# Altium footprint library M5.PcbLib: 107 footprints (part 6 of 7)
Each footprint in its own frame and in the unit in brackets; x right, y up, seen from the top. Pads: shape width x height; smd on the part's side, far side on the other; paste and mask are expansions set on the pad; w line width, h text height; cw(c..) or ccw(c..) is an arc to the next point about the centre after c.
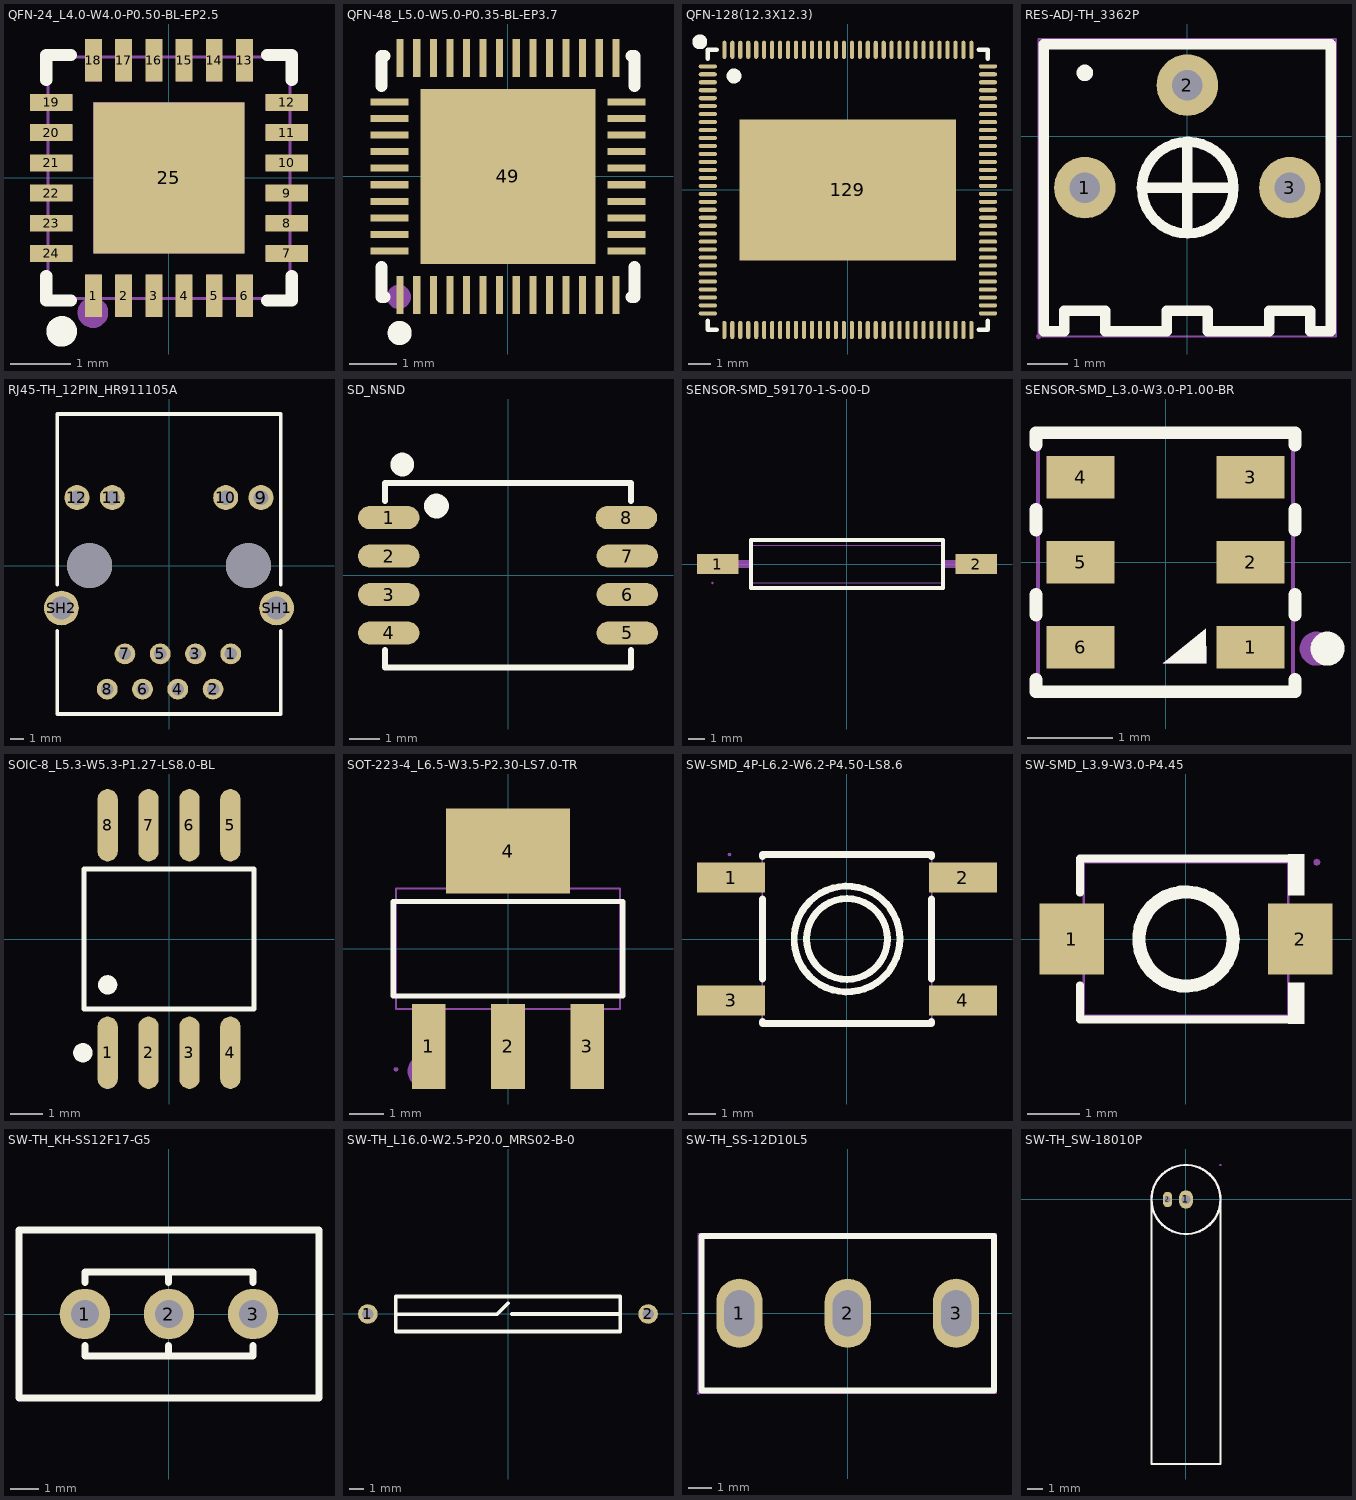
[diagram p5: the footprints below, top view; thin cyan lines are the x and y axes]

## QFN-24_L4.0-W4.0-P0.50-BL-EP2.5 [mm]
pads (25):
  rect 0.28x0.7 smd paste-100 mask+0.05: 1(-1.25,-1.95) 2(-0.75,-1.95) 3(-0.25,-1.95) 4(0.25,-1.95) 5(0.75,-1.95) 6(1.25,-1.95) 13(1.25,1.95) 14(0.75,1.95) 15(0.25,1.95) 16(-0.25,1.95) 17(-0.75,1.95) 18(-1.25,1.95)
  rect 0.7x0.28 smd paste-100 mask+0.05: 7(1.95,-1.25) 8(1.95,-0.75) 9(1.95,-0.25) 10(1.95,0.25) 11(1.95,0.75) 12(1.95,1.25) 19(-1.95,1.25) 20(-1.95,0.75) 21(-1.95,0.25) 22(-1.95,-0.25) 23(-1.95,-0.75) 24(-1.95,-1.25)
  rect 2.5x2.5 smd paste-100 mask+0.05: 25(0,0)
Top Overlay:
  circle w0.254: c-1.778,-2.54 r0.127
  lines w0.2: -2.032,-1.621 -2.032,-2.032 -1.621,-2.032 ; -2.032,1.621 -2.032,2.032 -1.621,2.032 ; 1.621,-2.032 2.032,-2.032 2.032,-1.621 ; 1.621,2.032 2.032,2.032 2.032,1.621
Top Paste:
  region: -1.39,1.6 -1.11,1.6 -1.11,2.3 -1.39,2.3
  region: -0.89,1.6 -0.61,1.6 -0.61,2.3 -0.89,2.3
  region: -0.39,1.6 -0.11,1.6 -0.11,2.3 -0.39,2.3
  region: 0.11,1.6 0.39,1.6 0.39,2.3 0.11,2.3
  region: 0.61,1.6 0.89,1.6 0.89,2.3 0.61,2.3
  region: 1.11,1.6 1.39,1.6 1.39,2.3 1.11,2.3
  region: -1.39,-2.3 -1.11,-2.3 -1.11,-1.6 -1.39,-1.6
  region: -0.89,-2.3 -0.61,-2.3 -0.61,-1.6 -0.89,-1.6
  region: -0.39,-2.3 -0.11,-2.3 -0.11,-1.6 -0.39,-1.6
  region: 0.11,-2.3 0.39,-2.3 0.39,-1.6 0.11,-1.6
  region: 0.61,-2.3 0.89,-2.3 0.89,-1.6 0.61,-1.6
  region: 1.11,-2.3 1.39,-2.3 1.39,-1.6 1.11,-1.6
  region: 1.6,1.39 1.6,1.11 2.3,1.11 2.3,1.39
  region: 1.6,0.89 1.6,0.61 2.3,0.61 2.3,0.89
  region: 1.6,0.39 1.6,0.11 2.3,0.11 2.3,0.39
  region: 1.6,-0.11 1.6,-0.39 2.3,-0.39 2.3,-0.11
  region: 1.6,-0.61 1.6,-0.89 2.3,-0.89 2.3,-0.61
  region: 1.6,-1.11 1.6,-1.39 2.3,-1.39 2.3,-1.11
  region: -2.3,-1.11 -2.3,-1.39 -1.6,-1.39 -1.6,-1.11
  region: -2.3,-0.61 -2.3,-0.89 -1.6,-0.89 -1.6,-0.61
  region: -2.3,-0.11 -2.3,-0.39 -1.6,-0.39 -1.6,-0.11
  region: -2.3,0.39 -2.3,0.11 -1.6,0.11 -1.6,0.39
  region: -2.3,0.89 -2.3,0.61 -1.6,0.61 -1.6,0.89
  region: -2.3,1.39 -2.3,1.11 -1.6,1.11 -1.6,1.39
  region: -1,-1 -1,1 1,1 1,-1
Mechanical 6:
  circle w0.254: c-1.26,-2.23 r0.127
Mechanical 15:
  region: -1.25,-1.25 -1.25,1.25 1.25,1.25 1.25,-1.25
  region: -1.125,-2 -1.375,-2 -1.375,-1.6 -1.125,-1.6
  region: -0.625,-2 -0.875,-2 -0.875,-1.6 -0.625,-1.6
  region: -0.125,-2 -0.375,-2 -0.375,-1.6 -0.125,-1.6
  region: 0.375,-2 0.125,-2 0.125,-1.6 0.375,-1.6
  region: 0.875,-2 0.625,-2 0.625,-1.6 0.875,-1.6
  region: 1.375,-2 1.125,-2 1.125,-1.6 1.375,-1.6
  region: 1.6,-1.375 1.6,-1.125 2,-1.125 2,-1.375
  region: 1.6,-0.875 1.6,-0.625 2,-0.625 2,-0.875
  region: 1.6,-0.375 1.6,-0.125 2,-0.125 2,-0.375
  region: 1.6,0.125 1.6,0.375 2,0.375 2,0.125
  region: 1.6,0.625 1.6,0.875 2,0.875 2,0.625
  region: 1.6,1.125 1.6,1.375 2,1.375 2,1.125
  region: 1.125,2 1.375,2 1.375,1.6 1.125,1.6
  region: 0.625,2 0.875,2 0.875,1.6 0.625,1.6
  region: 0.125,2 0.375,2 0.375,1.6 0.125,1.6
  region: -0.375,2 -0.125,2 -0.125,1.6 -0.375,1.6
  region: -0.875,2 -0.625,2 -0.625,1.6 -0.875,1.6
  region: -1.375,2 -1.125,2 -1.125,1.6 -1.375,1.6
  region: -1.6,1.375 -1.6,1.125 -2,1.125 -2,1.375
  region: -1.6,0.875 -1.6,0.625 -2,0.625 -2,0.875
  region: -1.6,0.375 -1.6,0.125 -2,0.125 -2,0.375
  region: -1.6,-0.125 -1.6,-0.375 -2,-0.375 -2,-0.125
  region: -1.6,-0.625 -1.6,-0.875 -2,-0.875 -2,-0.625
  region: -1.6,-1.125 -1.6,-1.375 -2,-1.375 -2,-1.125
  region: -1.936,-2 -1.954,-1.956 -2,-1.937 -2.046,-1.956 -2.064,-2 -2.046,-2.045 -2,-2.064 -1.954,-2.045
  lines w0.051: -2,-2 -2,2 2,2 2,-2 -2,-2
3D body: height 0.55, standoff 0, extent -2.01,-2.01 2.01,2.01

## QFN-48_L5.0-W5.0-P0.35-BL-EP3.7 [mm]
pads (49):
  rect 0.15x0.8 smd paste-100 mask+0.05: 1(-2.275,-2.5) 2(-1.925,-2.5) 3(-1.575,-2.5) 4(-1.225,-2.5) 5(-0.875,-2.5) 6(-0.525,-2.5) 7(-0.175,-2.5) 8(0.175,-2.5) 9(0.525,-2.5) 10(0.875,-2.5) 11(1.225,-2.5) 12(1.575,-2.5) 13(1.925,-2.5) 14(2.275,-2.5) 25(2.275,2.5) 26(1.925,2.5) 27(1.575,2.5) 28(1.225,2.5) 29(0.875,2.5) 30(0.525,2.5) 31(0.175,2.5) 32(-0.175,2.5) 33(-0.525,2.5) 34(-0.875,2.5) 35(-1.225,2.5) 36(-1.575,2.5) 37(-1.925,2.5) 38(-2.275,2.5)
  rect 0.8x0.15 smd paste-100 mask+0.05: 15(2.5,-1.575) 16(2.5,-1.225) 17(2.5,-0.875) 18(2.5,-0.525) 19(2.5,-0.175) 20(2.5,0.175) 21(2.5,0.525) 22(2.5,0.875) 23(2.5,1.225) 24(2.5,1.575) 39(-2.5,1.575) 40(-2.5,1.225) 41(-2.5,0.875) 42(-2.5,0.525) 43(-2.5,0.175) 44(-2.5,-0.175) 45(-2.5,-0.525) 46(-2.5,-0.875) 47(-2.5,-1.225) 48(-2.5,-1.575)
  rect 3.7x3.7 smd paste-100 mask+0.05: 49(0,0)
Top Overlay:
  circle w0.254: c-2.286,-3.302 r0.127
  lines w0.254: -2.667,-1.906 -2.667,-2.54 -2.606,-2.54 ; -2.667,1.906 -2.667,2.54 -2.606,2.54 ; 2.606,-2.54 2.667,-2.54 2.667,-1.906 ; 2.606,2.54 2.667,2.54 2.667,1.906
Top Paste:
  drawing of 49 lines, arcs and shapes, not listed
Mechanical 6:
  circle w0.254: c-2.302,-2.54 r0.127

## QFN-128(12.3X12.3) [mm]
pads (129):
  oval 0.8x0.18 smd: 1(-6.15,5.425) 2(-6.15,5.075) 3(-6.15,4.725) 4(-6.15,4.375) 5(-6.15,4.025) 6(-6.15,3.675) 7(-6.15,3.325) 8(-6.15,2.975) 9(-6.15,2.625) 10(-6.15,2.275) 11(-6.15,1.925) 12(-6.15,1.575) 13(-6.15,1.225) 14(-6.15,0.875) 15(-6.15,0.525) 16(-6.15,0.175) 17(-6.15,-0.175) 18(-6.15,-0.525) 19(-6.15,-0.875) 20(-6.15,-1.225) 21(-6.15,-1.575) 22(-6.15,-1.925) 23(-6.15,-2.275) 24(-6.15,-2.625) 25(-6.15,-2.975) 26(-6.15,-3.325) 27(-6.15,-3.675) 28(-6.15,-4.025) 29(-6.15,-4.375) 30(-6.15,-4.725) 31(-6.15,-5.075) 32(-6.15,-5.425) 65(6.15,-5.425) 66(6.15,-5.075) 67(6.15,-4.725) 68(6.15,-4.375) 69(6.15,-4.025) 70(6.15,-3.675) 71(6.15,-3.325) 72(6.15,-2.975) 73(6.15,-2.625) 74(6.15,-2.275) 75(6.15,-1.925) 76(6.15,-1.575) 77(6.15,-1.225) 78(6.15,-0.875) 79(6.15,-0.525) 80(6.15,-0.175) 81(6.15,0.175) 82(6.15,0.525) 83(6.15,0.875) 84(6.15,1.225) 85(6.15,1.575) 86(6.15,1.925) 87(6.15,2.275) 88(6.15,2.625) 89(6.15,2.975) 90(6.15,3.325) 91(6.15,3.675) 92(6.15,4.025) 93(6.15,4.375) 94(6.15,4.725) 95(6.15,5.075) 96(6.15,5.425)
  oval 0.18x0.8 smd: 33(-5.425,-6.15) 34(-5.075,-6.15) 35(-4.725,-6.15) 36(-4.375,-6.15) 37(-4.025,-6.15) 38(-3.675,-6.15) 39(-3.325,-6.15) 40(-2.975,-6.15) 41(-2.625,-6.15) 42(-2.275,-6.15) 43(-1.925,-6.15) 44(-1.575,-6.15) 45(-1.225,-6.15) 46(-0.875,-6.15) 47(-0.525,-6.15) 48(-0.175,-6.15) 49(0.175,-6.15) 50(0.525,-6.15) 51(0.875,-6.15) 52(1.225,-6.15) 53(1.575,-6.15) 54(1.925,-6.15) 55(2.275,-6.15) 56(2.625,-6.15) 57(2.975,-6.15) 58(3.325,-6.15) 59(3.675,-6.15) 60(4.025,-6.15) 61(4.375,-6.15) 62(4.725,-6.15) 63(5.075,-6.15) 64(5.425,-6.15) 97(5.425,6.15) 98(5.075,6.15) 99(4.725,6.15) 100(4.375,6.15) 101(4.025,6.15) 102(3.675,6.15) 103(3.325,6.15) 104(2.975,6.15) 105(2.625,6.15) 106(2.275,6.15) 107(1.925,6.15) 108(1.575,6.15) 109(1.225,6.15) 110(0.875,6.15) 111(0.525,6.15) 112(0.175,6.15) 113(-0.175,6.15) 114(-0.525,6.15) 115(-0.875,6.15) 116(-1.225,6.15) 117(-1.575,6.15) 118(-1.925,6.15) 119(-2.275,6.15) 120(-2.625,6.15) 121(-2.975,6.15) 122(-3.325,6.15) 123(-3.675,6.15) 124(-4.025,6.15) 125(-4.375,6.15) 126(-4.725,6.15) 127(-5.075,6.15) 128(-5.425,6.15)
  rect 9.5x6.2 smd: 129(0,0)
Top Overlay:
  circle w0.4: c-6.5,6.5 r0.125
  circle w0.4: c-5,5 r0.125
  lines w0.2: -6.15,-5.75 -6.15,-6.15 -5.75,-6.15 ; -6.15,5.75 -6.15,6.15 -5.75,6.15 ; 5.75,-6.15 6.15,-6.15 6.15,-5.75 ; 5.75,6.15 6.15,6.15 6.15,5.75

## RES-ADJ-TH_3362P [mil]
pads (3):
  round 60 hole 30: 1(-100,-50) 2(0,50) 3(100,-50)
Top Overlay:
  lines w10: -100,65 ccw(c-99.95,62) -99.95,59 ccw(c-99.95,62) -99.9,65 ; -40,-50 40,-50 ; 0,-90 0,-10 ; 0,-5.3 ccw(c0.4,-50.02) 0.4,-94.74 ccw(c0.4,-50.02) 0.8,-5.3 ; 140,-30 140,90 -140,90 -140,-30 -140,-170 -140,-190 -120,-190 -120,-170 -80,-170 -80,-190 -20,-190 -20,-170 20,-170 20,-190 80,-190 80,-170 120,-170 120,-190 140,-190 140,-170 140,-10
Mechanical 15:
  region: -142.44,-195 -143.19,-193.19 -145,-192.44 -146.81,-193.19 -147.56,-195 -146.81,-196.81 -145,-197.56 -143.19,-196.81 -142.44,-195
  region: -88.74,-50 -89.58,-45.76 -92.02,-42.1 -95.68,-39.65 -100,-38.8 -104.32,-39.65 -107.98,-42.1 -110.42,-45.76 -111.26,-50 -110.42,-54.24 -107.98,-57.9 -104.32,-60.35 -100,-61.21 -95.68,-60.35 -92.02,-57.9 -89.58,-54.24
  region: 11.26,50 10.42,54.24 7.98,57.9 4.32,60.35 0,61.2 -4.32,60.35 -7.98,57.9 -10.42,54.24 -11.26,50 -10.42,45.76 -7.98,42.1 -4.32,39.65 0,38.79 4.32,39.65 7.98,42.1 10.42,45.76
  region: 111.26,-50 110.42,-45.76 107.98,-42.1 104.32,-39.65 100,-38.8 95.68,-39.65 92.02,-42.1 89.58,-45.76 88.74,-50 89.58,-54.24 92.02,-57.9 95.68,-60.35 100,-61.21 104.32,-60.35 107.98,-57.9 110.42,-54.24
  lines w2: -145,-195 -145,95 145,95 145,-195 -145,-195

## RJ45-TH_12PIN_HR911105A [mm]
pads (16):
  round 1.5 hole 0.9: 1(4.445,-6.355) 2(3.175,-8.895) 3(1.905,-6.355) 4(0.635,-8.895) 5(-0.635,-6.355) 6(-1.905,-8.895) 7(-3.175,-6.355) 8(-4.445,-8.895)
  round 1.8 hole 1.05: 9(6.625,4.895) 10(4.085,4.895) 11(-4.085,4.895) 12(-6.625,4.895)
  round 2.5 hole 1.65: SH1(7.745,-3.055) SH2(-7.745,-3.055)
  round 3.25 hole 3.25 unplated: ""(-5.715,-0.005) ""(5.715,-0.005)
Top Overlay:
  lines w0.254: -8.05,-4.685 -8.05,-10.685 8.05,-10.685 8.05,-4.685 ; -8.05,-1.385 -8.05,10.915 ; -8.05,10.915 8.05,10.915 8.05,-1.385

## SD_NSND [mm]
pads (8):
  oval 2x0.75 smd: 1(-3.875,1.875) 2(-3.875,0.625) 3(-3.875,-0.625) 4(-3.875,-1.875) 5(3.875,-1.875) 6(3.875,-0.625) 7(3.875,0.625) 8(3.85,1.875)
Top Overlay:
  circle w0.5: c-2.325,2.25 r0.152
  circle w0.5: c-3.435,3.6 r0.135
  lines w0.2: -4,-2.425 -4,-3 4,-3 4,-2.425 ; -4,2.425 -4,3 4,3 4,2.425

## SENSOR-SMD_59170-1-S-00-D [mm]
pads (2):
  rect 2.5x1.2 smd: 1(-7.8,0) 2(7.8,0)
Top Overlay:
  lines w0.254: -5.8,-1.45 -5.8,1.45 5.8,1.45 5.8,-1.45 -5.8,-1.45
Mechanical 15:
  region: -8.125,-0.215 -8.125,0.215 -6.605,0.215 -6.605,-0.215
  region: -6.615,-0.215 -6.615,0.215 -5.705,0.215 -5.705,-0.215
  region: 6.605,-0.215 6.605,0.215 8.125,0.215 8.125,-0.215
  region: 5.705,-0.215 5.705,0.215 6.615,0.215 6.615,-0.215
  region: -8.06,-1.145 -8.079,-1.191 -8.125,-1.21 -8.171,-1.191 -8.19,-1.145 -8.171,-1.099 -8.125,-1.08 -8.079,-1.099
  lines w0.051: -5.715,-1.145 5.715,-1.145 5.715,1.145 -5.715,1.145 -5.715,-1.145
3D body: height 2.41, standoff -0.03, extent -8.125,-1.145 8.125,1.145

## SENSOR-SMD_L3.0-W3.0-P1.00-BR [mm]
pads (6):
  rect 0.8x0.5 smd paste+0 mask+0.05: 1(1,-1) 2(1,0) 3(1,1) 4(-1,1) 5(-1,0) 6(-1,-1)
Top Overlay:
  circle w0.2: c1.905,-1.016 r0.1
  region: -0.028,-1.186 0.481,-1.187 0.476,-0.78
  lines w0.15: -1.524,-1.378 -1.524,-1.524 1.524,-1.524 1.524,-1.378 ; -1.524,-0.622 -1.524,-0.378 ; -1.524,0.378 -1.524,0.622 ; -1.524,1.378 -1.524,1.524 1.524,1.524 1.524,1.378 ; 1.524,-0.622 1.524,-0.378 ; 1.524,0.378 1.524,0.622
Mechanical 6:
  circle w0.2: c1.778,-1.016 r0.1
  region: -0.032,-1.186 0.477,-1.187 0.472,-0.781
Mechanical 15:
  region: 1.565,-1.5 1.546,-1.546 1.5,-1.565 1.454,-1.546 1.435,-1.5 1.454,-1.454 1.5,-1.435 1.546,-1.454
  region: -0.725,0.8 -1.275,0.8 -1.275,1.2 -0.725,1.2
  region: -0.725,-0.2 -1.275,-0.2 -1.275,0.2 -0.725,0.2
  region: -0.725,-1.2 -1.275,-1.2 -1.275,-0.8 -0.725,-0.8
  region: 1.275,-1.2 0.725,-1.2 0.725,-0.8 1.275,-0.8
  region: 1.275,-0.2 0.725,-0.2 0.725,0.2 1.275,0.2
  region: 1.275,0.8 0.725,0.8 0.725,1.2 1.275,1.2
  lines w0.051: -1.5,-1.5 -1.5,1.5 1.5,1.5 1.5,-1.5 -1.5,-1.5

## SOIC-8_L5.3-W5.3-P1.27-LS8.0-BL [mm]
pads (8):
  oval 0.63x2.25 smd: 1(-1.905,-3.53) 2(-0.635,-3.53) 3(0.635,-3.53) 4(1.905,-3.53) 5(1.905,3.53) 6(0.635,3.53) 7(-0.635,3.53) 8(-1.905,3.53)
Top Overlay:
  circle w0.3: c-2.672,-3.53 r0.15
  circle w0.3: c-1.905,-1.424 r0.15
  lines w0.152: -2.639,-2.176 2.639,-2.176 2.639,2.176 -2.639,2.176 -2.639,-2.176
Mechanical 6:
  circle w0.3: c-1.905,-4.35 r0.15
3D body: height 1.91, standoff -0.05, extent -2.502,-3.226 2.502,2.972

## SOT-223-4_L6.5-W3.5-P2.30-LS7.0-TR [mm]
pads (4):
  rect 0.98x2.47 smd: 1(-2.3,-2.835) 2(0,-2.835) 3(2.3,-2.835)
  rect 3.6x2.47 smd: 4(0,2.835)
Top Overlay:
  lines w0.152: -3.326,-1.371 3.326,-1.371 3.326,1.371 -3.326,1.371 -3.326,-1.371
Mechanical 6:
  circle w0.5: c-2.413,-3.556 r0.25
Mechanical 15:
  region: -3.185,-3.5 -3.204,-3.546 -3.25,-3.565 -3.296,-3.546 -3.315,-3.5 -3.296,-3.454 -3.25,-3.435 -3.204,-3.454
  region: -1.5,2.56 1.5,2.56 1.5,1.74 -1.5,1.74
  region: -1.5,2.55 1.5,2.55 1.5,3.5 -1.5,3.5
  region: 1.95,-1.74 2.65,-1.74 2.65,-2.56 1.95,-2.56
  region: 1.95,-2.55 2.65,-2.55 2.65,-3.5 1.95,-3.5
  region: -0.35,-1.74 0.35,-1.74 0.35,-2.56 -0.35,-2.56
  region: -0.35,-2.55 0.35,-2.55 0.35,-3.5 -0.35,-3.5
  region: -2.65,-1.74 -1.95,-1.74 -1.95,-2.56 -2.65,-2.56
  region: -2.65,-2.55 -1.95,-2.55 -1.95,-3.5 -2.65,-3.5
  lines w0.051: -3.25,-1.75 3.25,-1.75 3.25,1.75 -3.25,1.75 -3.25,-1.75
3D body: height 1.8, standoff 0, extent -3.253,-3.373 3.252,3.627

## SW-SMD_4P-L6.2-W6.2-P4.50-LS8.6 [mm]
pads (4):
  rect 2.5x1.1 smd: 1(-4.25,2.25) 2(4.25,2.25) 3(-4.25,-2.25) 4(4.25,-2.25)
Top Overlay:
  circle w0.254: c0,0 r1.481
  circle w0.254: c0,0 r1.939
  lines w0.254: -3.1,-3.031 -3.1,-3.1 3.1,-3.1 3.1,-3.031 ; -3.1,-1.469 -3.1,1.469 ; -3.1,3.031 -3.1,3.1 3.1,3.1 3.1,3.031 ; 3.1,-1.469 3.1,1.469
Mechanical 15:
  region: -3.5,1.9 -4.301,1.9 -4.301,2.6 -3.5,2.6
  region: -3.048,1.9 -3.55,1.9 -3.55,2.6 -3.048,2.6
  region: -3.5,-2.6 -4.301,-2.6 -4.301,-1.9 -3.5,-1.9
  region: -3.048,-2.6 -3.55,-2.6 -3.55,-1.9 -3.048,-1.9
  region: 3.5,-1.9 4.301,-1.9 4.301,-2.6 3.5,-2.6
  region: 3.048,-1.9 3.55,-1.9 3.55,-2.6 3.048,-2.6
  region: 3.048,2.6 3.55,2.6 3.55,1.9 3.048,1.9
  region: 3.5,2.6 4.301,2.6 4.301,1.9 3.5,1.9
  region: -4.236,3.1 -4.255,3.054 -4.301,3.035 -4.347,3.054 -4.366,3.1 -4.347,3.146 -4.301,3.165 -4.255,3.146
  lines w0.051: -3.1,-3.1 3.1,-3.1 3.1,3.1 -3.1,3.1 -3.1,-3.1

## SW-SMD_L3.9-W3.0-P4.45 [mm]
pads (2):
  rect 1.23x1.36 smd: 1(-2.185,0) 2(2.185,0)
Top Overlay:
  circle w0.254: c0,0 r0.9
  region: 1.95,1.617 1.95,0.832 2.255,0.832 2.255,1.617
  region: 1.95,-1.617 1.95,-0.832 2.255,-0.832 2.255,-1.617
  lines w0.152: -2.026,-0.883 -2.026,-1.541 2.026,-1.541 ; -2.026,0.883 -2.026,1.541 2.026,1.541
Mechanical 15:
  region: -2.5,0.65 -2.5,-0.65 -1.6,-0.65 -1.6,0.65
  region: 2.5,0.65 2.5,-0.65 1.6,-0.65 1.6,0.65
  region: 2.565,1.465 2.546,1.419 2.5,1.4 2.454,1.419 2.435,1.465 2.454,1.511 2.5,1.53 2.546,1.511
  lines w0.051: -1.95,-1.465 -1.95,1.465 1.95,1.465 1.95,-1.465 -1.95,-1.465
3D body: height 2, standoff 0, extent -3.341,-3.337 3.341,3.338

## SW-TH_KH-SS12F17-G5 [mm]
pads (3):
  round 1.8 hole 1 paste+0 mask+0.05: 1(-3,0) 2(0,0) 3(3,0)
Top Overlay:
  lines w0.254: -3,-1.131 -3,-1.5 ; -3,1.131 -3,1.5 3,1.5 3,1.131 ; -0.013,-1.5 -0.013,-1.131 ; -0.013,1.131 -0.013,1.5 ; 3,-1.131 3,-1.5 -3,-1.5 ; -3,-1.5 -3,-1.5 ; -5.35,-3 -5.35,3 5.35,3 5.35,-3 -5.35,-3
3D body: height 8.54, standoff -3.86, extent -5.35,-2.921 5.35,2.879

## SW-TH_L16.0-W2.5-P20.0_MRS02-B-0 [mm]
pads (2):
  round 1.4 hole 0.8 paste+0 mask+0.05: 1(-10,0) 2(10,0)
Top Overlay:
  lines w0.254: -8,-0.006 -0.768,-0.006 0,0.762 ; 0.254,0 8,0 ; -8,-1.25 -8,1.25 8,1.25 8,-1.25 -8,-1.25

## SW-TH_SS-12D10L5 [mm]
pads (3):
  oval 2x3 hole 1.3 slot 2 at 90 deg: 1(-4.7,0) 2(0,0) 3(4.7,0)
Top Overlay:
  lines w0.254: -6.35,-3.35 -6.35,3.35 6.35,3.35 6.35,-3.35 -6.35,-3.35
Mechanical 15:
  region: -5.1,0.65 -4.3,0.65 -4.3,-0.65 -5.1,-0.65
  region: -0.4,0.65 0.4,0.65 0.4,-0.65 -0.4,-0.65
  region: 4.3,0.65 5.1,0.65 5.1,-0.65 4.3,-0.65
  region: -6.412,-3.477 -6.431,-3.523 -6.477,-3.542 -6.523,-3.523 -6.542,-3.477 -6.523,-3.431 -6.477,-3.412 -6.431,-3.431
  lines w0.051: -6.477,-3.477 -6.477,3.477 6.477,3.477 6.477,-3.477 -6.477,-3.477

## SW-TH_SW-18010P [mm]
pads (2):
  oval 0.9x1.2 hole 0.6: 1(0,0)
  oval 0.6x1 hole 0.4: 2(-1.2,0)
Top Overlay:
  circle w0.152: c0,0 r2.25
  lines w0.152: -2.25,0 -2.25,-17.25 2.25,-17.25 2.25,0
Mechanical 6:
  region: 0,-2.311 -0.451,-2.267 -0.884,-2.135 -1.284,-1.922 -1.634,-1.634 -1.922,-1.284 -2.135,-0.884 -2.267,-0.451 -2.311,0 -2.3,0 -2.211,0 -2.168,-0.431 -2.042,-0.846 -1.838,-1.228 -1.563,-1.563 -1.228,-1.838 -0.846,-2.042 -0.431,-2.168 0,-2.211 0,-2.2
  region: -2.311,0 -2.267,0.451 -2.135,0.884 -1.922,1.284 -1.634,1.634 -1.284,1.922 -0.884,2.135 -0.451,2.267 0,2.311 0,2.3 0,2.211 -0.431,2.168 -0.846,2.042 -1.228,1.838 -1.563,1.563 -1.838,1.228 -2.042,0.846 -2.168,0.431 -2.211,0 -2.2,0
  region: 0,2.311 0.451,2.267 0.884,2.135 1.284,1.922 1.634,1.634 1.922,1.284 2.135,0.884 2.267,0.451 2.311,0 2.3,0 2.211,0 2.168,0.431 2.042,0.846 1.838,1.228 1.563,1.563 1.228,1.838 0.846,2.042 0.431,2.168 0,2.211 0,2.2
  region: 2.311,0 2.267,-0.451 2.135,-0.884 1.922,-1.284 1.634,-1.634 1.284,-1.922 0.884,-2.135 0.451,-2.267 0,-2.311 0,-2.3 0,-2.211 0.431,-2.168 0.846,-2.042 1.228,-1.838 1.563,-1.563 1.838,-1.228 2.042,-0.846 2.168,-0.431 2.211,0 2.2,0
Mechanical 15:
  region: 0.255,0 0.235,-0.098 0.18,-0.18 0.098,-0.235 0,-0.255 -0.098,-0.235 -0.18,-0.18 -0.235,-0.098 -0.255,0 -0.235,0.098 -0.18,0.18 -0.098,0.235 0,0.255 0.098,0.235 0.18,0.18 0.235,0.098
  region: -1.119,0 -1.142,-0.057 -1.2,-0.081 -1.257,-0.057 -1.281,0 -1.257,0.057 -1.2,0.081 -1.142,0.057
  region: 2.314,2.25 2.295,2.204 2.249,2.185 2.203,2.204 2.184,2.25 2.203,2.296 2.249,2.315 2.295,2.296
  lines w0.051: -2.251,0 ccw(c-0.001,0) 2.249,0 ccw(c-0.001,0) -2.251,0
